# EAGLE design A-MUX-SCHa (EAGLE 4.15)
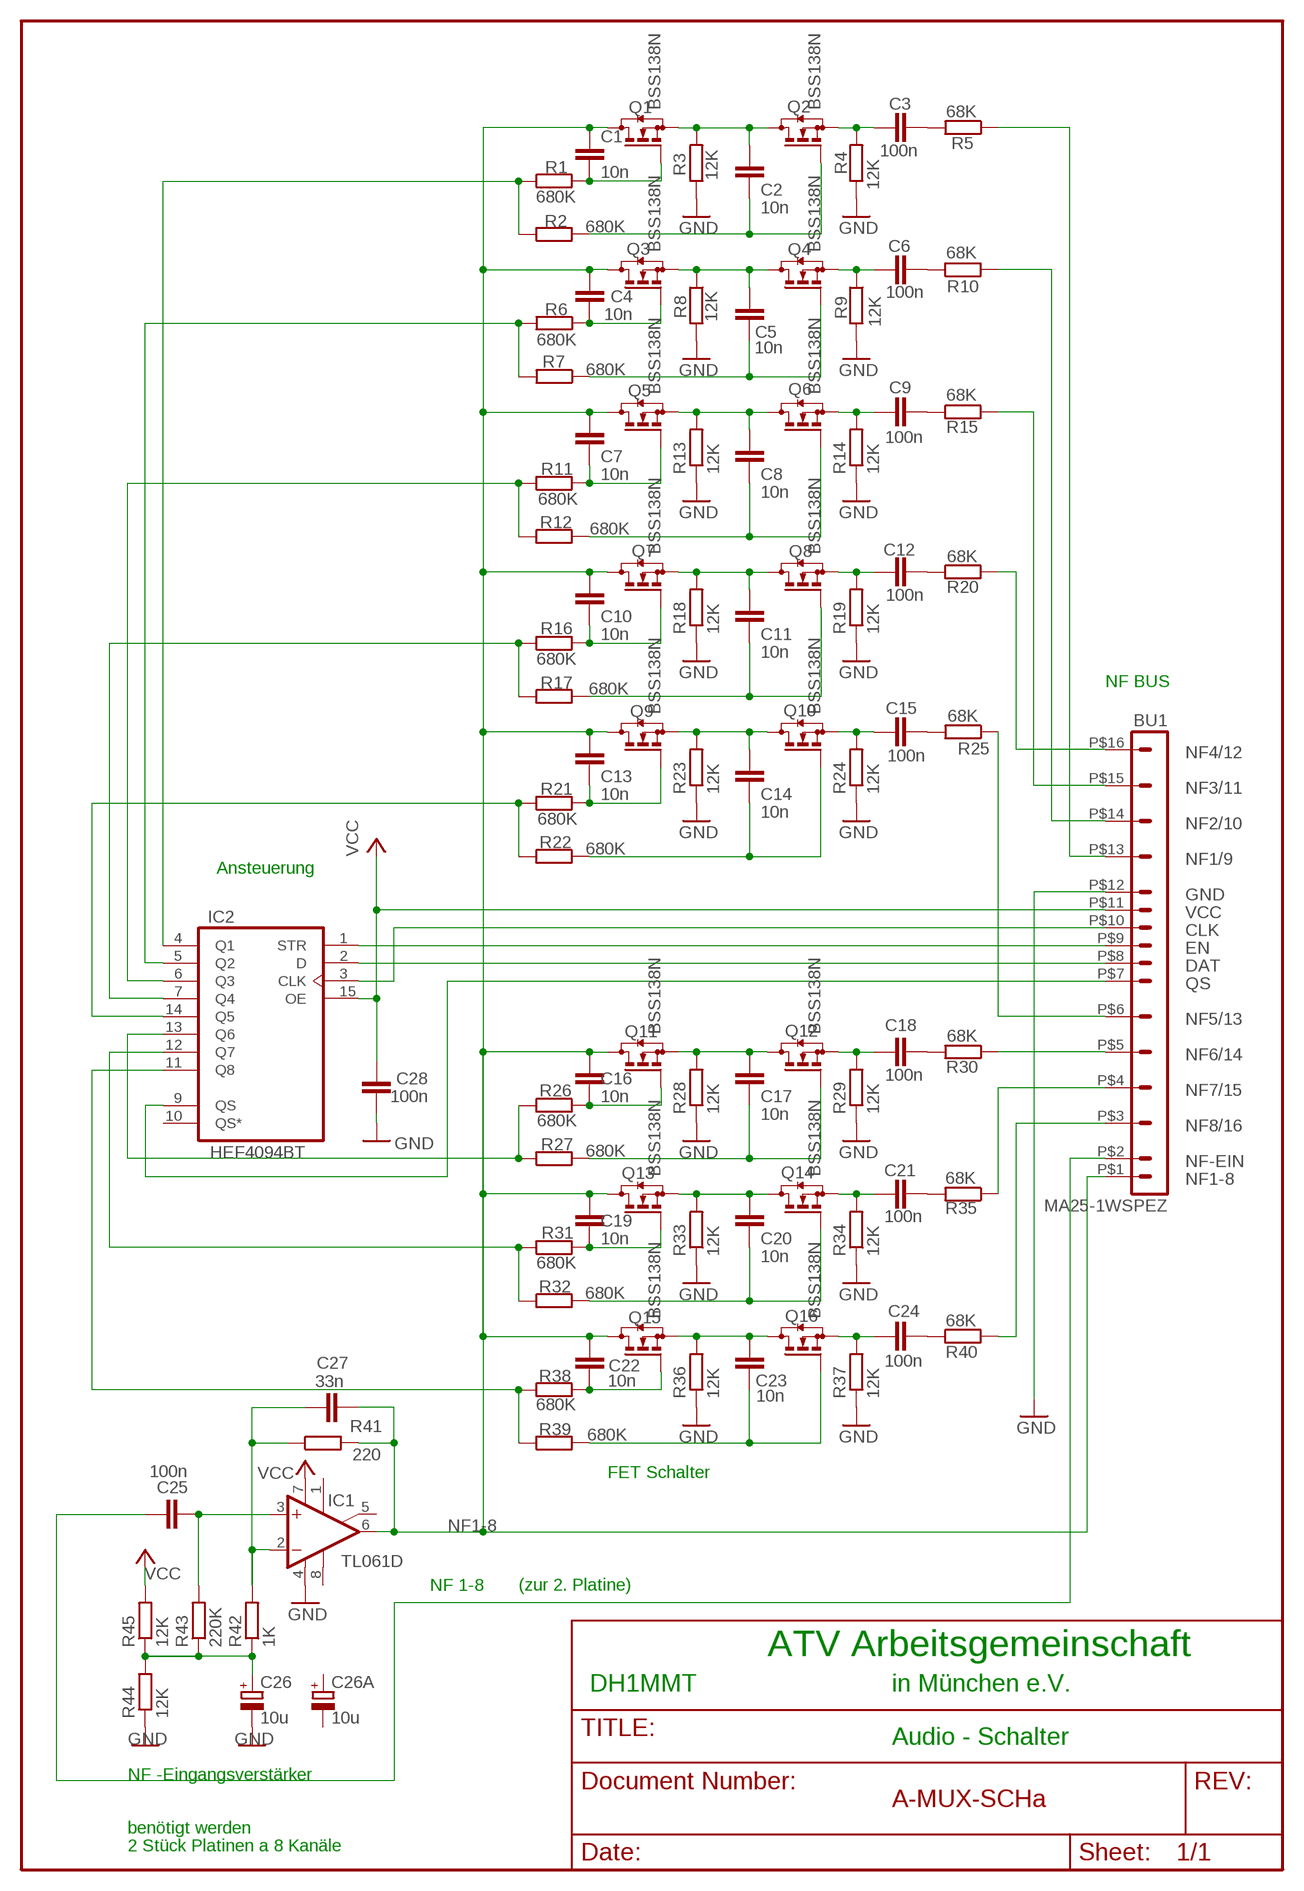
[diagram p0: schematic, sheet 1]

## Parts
BU1  MA25-1WSPEZ  [MA25-1WSPEZ]
C1  10n  C-EUC0603K  [C0603K]
C2  10n  C-EUC0603K  [C0603K]
C3  100n  C-EUC0603K  [C0603K]
C4  10n  C-EUC0603K  [C0603K]
C5  10n  C-EUC0603K  [C0603K]
C6  100n  C-EUC0603K  [C0603K]
C7  10n  C-EUC0603K  [C0603K]
C8  10n  C-EUC0603K  [C0603K]
C9  100n  C-EUC0603K  [C0603K]
C10  10n  C-EUC0603K  [C0603K]
C11  10n  C-EUC0603K  [C0603K]
C12  100n  C-EUC0603K  [C0603K]
C13  10n  C-EUC0603K  [C0603K]
C14  10n  C-EUC0603K  [C0603K]
C15  100n  C-EUC0603K  [C0603K]
C16  10n  C-EUC0603K  [C0603K]
C17  10n  C-EUC0603K  [C0603K]
C18  100n  C-EUC0603K  [C0603K]
C19  10n  C-EUC0603K  [C0603K]
C20  10n  C-EUC0603K  [C0603K]
C21  100n  C-EUC0603K  [C0603K]
C22  10n  C-EUC0603K  [C0603K]
C23  10n  C-EUC0603K  [C0603K]
C24  100n  C-EUC0603K  [C0603K]
C25  100n  C-EUC0603K  [C0603K]
C26  10u  CPOL-EUSMCB  [SMC_B]
C26A  10u  CPOL-EUE1.8-4  [E1,8-4]
C27  33n  C-EUC0603K  [C0603K]
C28  100n  C-EUC0603K  [C0603K]
IC1  TL061D  [SO08]
IC2  HEF4094BT  4094D  [SO16]
Q1  BSS138N  BSS123  [SOT23]
Q2  BSS138N  BSS123  [SOT23]
Q3  BSS138N  BSS123  [SOT23]
Q4  BSS138N  BSS123  [SOT23]
Q5  BSS138N  BSS123  [SOT23]
Q6  BSS138N  BSS123  [SOT23]
Q7  BSS138N  BSS123  [SOT23]
Q8  BSS138N  BSS123  [SOT23]
Q9  BSS138N  BSS123  [SOT23]
Q10  BSS138N  BSS123  [SOT23]
Q11  BSS138N  BSS123  [SOT23]
Q12  BSS138N  BSS123  [SOT23]
Q13  BSS138N  BSS123  [SOT23]
Q14  BSS138N  BSS123  [SOT23]
Q15  BSS138N  BSS123  [SOT23]
Q16  BSS138N  BSS123  [SOT23]
R1  680K  R-EU_MELF0204W  [MINI_MELF-0204W]
R2  680K  R-EU_MELF0204W  [MINI_MELF-0204W]
R3  12K  R-EU_MELF0204W  [MINI_MELF-0204W]
R4  12K  R-EU_MELF0204W  [MINI_MELF-0204W]
R5  68K  R-EU_MELF0204W  [MINI_MELF-0204W]
R6  680K  R-EU_MELF0204W  [MINI_MELF-0204W]
R7  680K  R-EU_MELF0204W  [MINI_MELF-0204W]
R8  12K  R-EU_MELF0204W  [MINI_MELF-0204W]
R9  12K  R-EU_MELF0204W  [MINI_MELF-0204W]
R10  68K  R-EU_MELF0204W  [MINI_MELF-0204W]
R11  680K  R-EU_MELF0204W  [MINI_MELF-0204W]
R12  680K  R-EU_MELF0204W  [MINI_MELF-0204W]
R13  12K  R-EU_MELF0204W  [MINI_MELF-0204W]
R14  12K  R-EU_MELF0204W  [MINI_MELF-0204W]
R15  68K  R-EU_MELF0204W  [MINI_MELF-0204W]
R16  680K  R-EU_MELF0204W  [MINI_MELF-0204W]
R17  680K  R-EU_MELF0204W  [MINI_MELF-0204W]
R18  12K  R-EU_MELF0204W  [MINI_MELF-0204W]
R19  12K  R-EU_MELF0204W  [MINI_MELF-0204W]
R20  68K  R-EU_MELF0204W  [MINI_MELF-0204W]
R21  680K  R-EU_MELF0204W  [MINI_MELF-0204W]
R22  680K  R-EU_MELF0204W  [MINI_MELF-0204W]
R23  12K  R-EU_MELF0204W  [MINI_MELF-0204W]
R24  12K  R-EU_MELF0204W  [MINI_MELF-0204W]
R25  68K  R-EU_MELF0204W  [MINI_MELF-0204W]
R26  680K  R-EU_MELF0204W  [MINI_MELF-0204W]
R27  680K  R-EU_MELF0204W  [MINI_MELF-0204W]
R28  12K  R-EU_MELF0204W  [MINI_MELF-0204W]
R29  12K  R-EU_MELF0204W  [MINI_MELF-0204W]
R30  68K  R-EU_MELF0204W  [MINI_MELF-0204W]
R31  680K  R-EU_MELF0204W  [MINI_MELF-0204W]
R32  680K  R-EU_MELF0204W  [MINI_MELF-0204W]
R33  12K  R-EU_MELF0204W  [MINI_MELF-0204W]
R34  12K  R-EU_MELF0204W  [MINI_MELF-0204W]
R35  68K  R-EU_MELF0204W  [MINI_MELF-0204W]
R36  12K  R-EU_MELF0204W  [MINI_MELF-0204W]
R37  12K  R-EU_MELF0204W  [MINI_MELF-0204W]
R38  680K  R-EU_MELF0204W  [MINI_MELF-0204W]
R39  680K  R-EU_MELF0204W  [MINI_MELF-0204W]
R40  68K  R-EU_MELF0204W  [MINI_MELF-0204W]
R41  220  R-EU_MELF0204W  [MINI_MELF-0204W]
R42  1K  R-EU_MELF0204W  [MINI_MELF-0204W]
R43  220K  R-EU_MELF0204W  [MINI_MELF-0204W]
R44  12K  R-EU_MELF0204W  [MINI_MELF-0204W]
R45  12K  R-EU_0207/10  [0207/10]

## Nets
CLK: BU1.P$10 IC2.3(CLK)
DAT: BU1.P$8 IC2.2(D)
EN: BU1.P$9 IC2.1(STR)
GND: BU1.P$12 C26.- C28.2 IC1.4(V-) R3.1 R4.1 R8.2 R9.2 R13.1 R14.1 R18.1 R19.1 R23.1 R24.1 R28.1 R29.1 R33.1 R34.1 R36.1 R37.1 R44.1
N$2: C1.2 Q1.1(G) R1.2
N$4: C2.1 Q1.2(S) Q2.3(D) R3.2
N$5: C2.2 Q2.1(G) R2.2
N$6: C3.1 Q2.2(S) R4.2
N$8: C3.2 R5.2
N$9: IC2.4(Q1) R1.1 R2.1
N$10: IC2.5(Q2) R6.2 R7.2
N$11: C4.1 Q3.1(G) R6.1
N$13: C5.2 Q3.2(S) Q4.3(D) R8.1
N$14: C5.1 Q4.1(G) R7.1
N$15: C6.1 R10.1
N$16: C6.2 Q4.2(S) R9.1
N$27: C9.1 R15.1
N$28: C12.1 R20.1
N$29: IC2.6(Q3) R11.1 R12.1
N$30: IC2.7(Q4) R16.1 R17.1
N$32: C11.1 Q7.2(S) Q8.3(D) R18.2
N$33: C12.2 Q8.2(S) R19.2
N$34: C11.2 Q8.1(G) R17.2
N$35: IC2.14(Q5) R21.1 R22.1
N$36: C10.2 Q7.1(G) R16.2
N$37: C7.2 Q5.1(G) R11.2
N$38: C8.2 Q6.1(G) R12.2
N$40: C8.1 Q5.2(S) Q6.3(D) R13.2
N$41: C9.2 Q6.2(S) R14.2
N$42: C13.2 Q9.1(G) R21.2
N$43: C14.2 Q10.1(G) R22.2
N$44: C15.2 Q10.2(S) R24.2
N$45: C14.1 Q9.2(S) Q10.3(D) R23.2
N$47: C15.1 R25.2
N$56: C18.1 R30.2
N$57: IC2.13(Q6) R26.1 R27.1
N$58: C17.2 Q12.1(G) R27.2
N$59: C18.2 Q12.2(S) R29.2
N$60: C17.1 Q11.2(S) Q12.3(D) R28.2
N$61: C16.2 Q11.1(G) R26.2
N$63: C21.1 R35.2
N$64: IC2.12(Q7) R31.1 R32.1
N$65: C20.2 Q14.1(G) R32.2
N$66: C19.2 Q13.1(G) R31.2
N$68: C20.1 Q13.2(S) Q14.3(D) R33.2
N$69: C21.2 Q14.2(S) R34.2
N$70: C24.1 R40.1
N$71: C23.1 Q15.2(S) Q16.3(D) R36.2
N$72: C22.2 Q15.1(G) R38.2
N$74: C23.2 Q16.1(G) R39.2
N$75: C24.2 Q16.2(S) R37.2
N$76: IC2.11(Q8) R38.1 R39.1
N$110: C25.2 IC1.3(+IN) R43.2
N$119: C27.1 IC1.2(-IN) R41.1 R42.2
N$152: C26.+ R42.1 R43.1 R44.2 R45.1
NF1-8: BU1.P$1 C1.1 C4.2 C7.1 C10.1 C13.1 C16.1 C19.1 C22.1 C27.2 IC1.6(OUT) Q1.3(D) Q3.3(D) Q5.3(D) Q7.3(D) Q9.3(D) Q11.3(D) Q13.3(D) Q15.3(D) R41.2
NF1/9: BU1.P$13 R5.1
NF2/10: BU1.P$14 R10.2
NF3/11: BU1.P$15 R15.2
NF4/12: BU1.P$16 R20.2
NF5/13: BU1.P$6 R25.1
NF6/14: BU1.P$5 R30.1
NF7/15: BU1.P$4 R35.1
NF8/16: BU1.P$3 R40.2
NF-EIN: BU1.P$2 C25.1
QS: BU1.P$7 IC2.9(QS)
VCC: BU1.P$11 C28.1 IC1.7(V+) IC2.15(OE) R45.2
Unconnected: C26A.+ C26A.- IC1.1(ON1) IC1.5(ON2) IC1.8(OPT) IC2.10(QS*)

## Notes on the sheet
- NF BUS
- Ansteuerung
- FET Schalter
- NF 1-8 | (zur 2. Platine)
- ATV Arbeitsgemeinschaft
- DH1MMT | in München e.V.
- Audio - Schalter
- NF -Eingangsverstärker
- benötigt werden
- 2 Stück Platinen a 8 Kanäle

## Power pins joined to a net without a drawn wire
VDD: IC2.16(VDD)
VSS: IC2.8(VSS)

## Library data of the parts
BU1 = con-lstb:MA25-1WSPEZ
C1-C25 C27 C28 = rcl:C-EU: CAPACITOR, European symbol
C26 C26A = rcl:CPOL-EU: POLARIZED CAPACITOR, European symbol
IC1 = linear:TL061: OP AMP
IC2 = 40xx:4094: 8-stage SHIFT/STORE REGISTER, tri-state
Q1-Q16 = transistor-small-signal:BSS123: N-CHANNEL MOS FET
R1-R45 = rcl:R-EU_: RESISTOR, European symbol

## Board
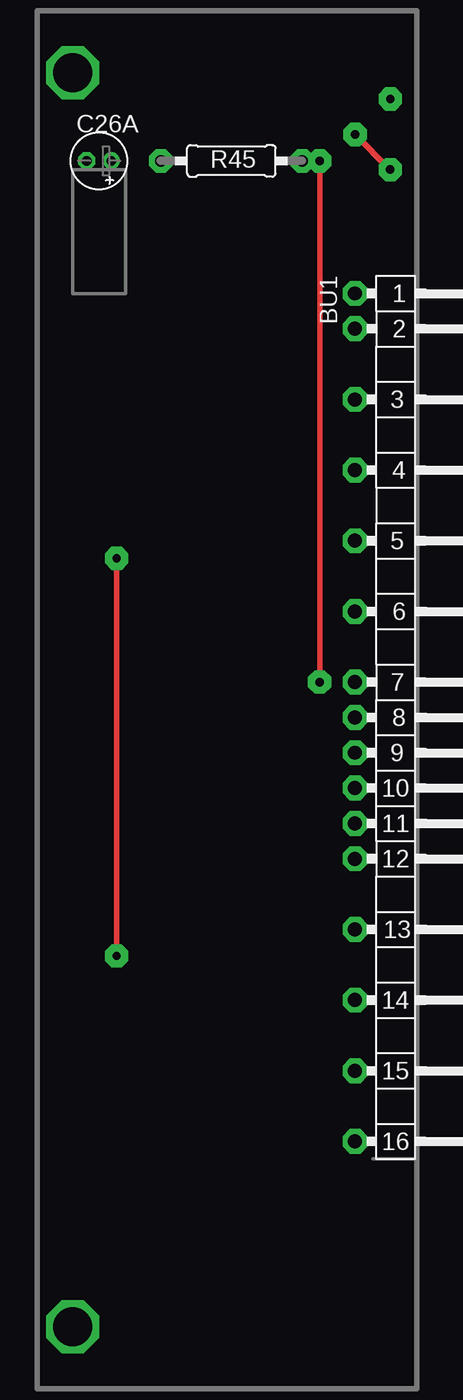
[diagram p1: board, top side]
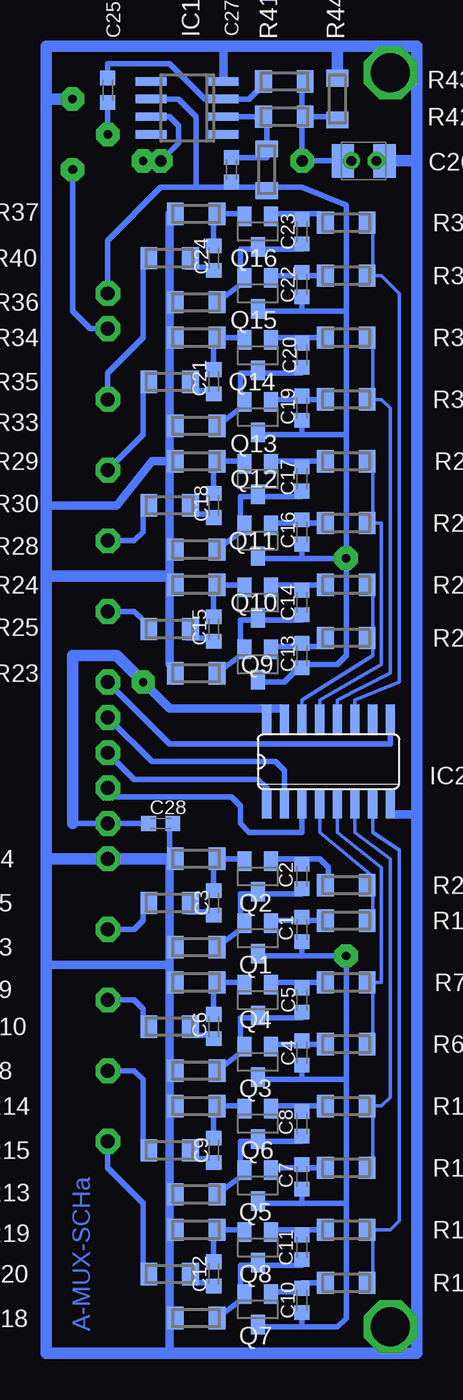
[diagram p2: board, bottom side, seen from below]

No outline drawn. Coordinates in mm, seen from the top.
Copper layers (1*16): Top 0.035mm / dielectric 1.5mm / Bottom 0.035mm
Design rules "default": minimum track width 10mil, minimum drill 24mil, track to track 8mil, track to pad 8mil, pad to pad 8mil, via to via 8mil, smd to smd 8mil, copper to edge 40mil, drill to drill 8mil, minimum pad ring 10mil, minimum via ring 8mil, stop-mask expansion 4mil, vias tented up to drill 0mil, thermal gap 10mil

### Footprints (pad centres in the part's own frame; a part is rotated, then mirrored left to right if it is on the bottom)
MA25-1WSPEZ = drill 1 pad 1.778 octagon: P$1 2.54,30.48; P$2 2.54,27.94; P$3 2.54,22.86; P$4 2.54,17.78; P$5 2.54,12.7; P$6 2.54,7.62; P$7 2.54,2.54; P$8 2.54,0; P$9 2.54,-2.54; P$10 2.54,-5.08; P$11 2.54,-7.62; P$12 2.54,-10.16; P$13 2.54,-15.24; P$14 2.54,-20.32; P$15 2.54,-25.4; P$16 2.54,-30.48
C0603K = smd 1.05 x 1.08: 1 -0.875,0; 2 0.875,0
SMC_B = smd 1.6 x 2.4: + -1.5,0; - 1.5,0
E1,8-4 = drill 0.711 pad 1.168 round: + -0.889,0 | drill 0.711 pad 1.168 octagon: - 0.889,0
SO08 = smd 0.6 x 2.2: 1 -1.905,-2.6; 2 -0.635,-2.6; 3 0.635,-2.6; 4 1.905,-2.6; 5 1.905,2.6; 6 0.635,2.6; 7 -0.635,2.6; 8 -1.905,2.6
SO16 = smd 0.66 x 2.032: 1 -4.445,-3.073; 2 -3.175,-3.073; 3 -1.905,-3.073; 4 -0.635,-3.073; 5 0.635,-3.073; 6 1.905,-3.073; 7 3.175,-3.073; 8 4.445,-3.073; 9 4.445,3.073; 10 3.175,3.073; 11 1.905,3.073; 12 0.635,3.073; 13 -0.635,3.073; 14 -1.905,3.073; 15 -3.175,3.073; 16 -4.445,3.073
SOT23 = smd 1 x 1.4: 1 -0.95,-1.1; 2 0.95,-1.1; 3 0,1.1
MINI_MELF-0204W = smd 1.2 x 1.6: 1 -1.5,0; 2 1.5,0
0207/10 = drill 0.813 octagon: 1 -5.08,0; 2 5.08,0

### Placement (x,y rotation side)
BU1  126.36,93.34 0 top
C1  114.94,78.11 90 bottom
C2  114.94,81.92 90 bottom
C3  121.28,80.01 270 bottom
C4  114.94,69.22 270 bottom
C5  114.94,73.03 270 bottom
C6  121.28,71.12 90 bottom
C7  114.94,60.33 90 bottom
C8  114.94,64.14 90 bottom
C9  121.28,62.23 90 bottom
C10  114.94,51.44 90 bottom
C11  114.94,55.24 90 bottom
C12  121.28,53.34 90 bottom
C13  114.94,97.79 90 bottom
C14  114.94,101.6 90 bottom
C15  121.28,99.69 90 bottom
C16  114.94,106.68 90 bottom
C17  114.94,110.49 90 bottom
C18  121.28,108.58 90 bottom
C19  114.94,115.57 90 bottom
C20  114.94,119.38 90 bottom
C21  121.28,117.47 90 bottom
C22  114.94,124.46 90 bottom
C23  114.94,128.27 90 bottom
C24  121.28,126.36 90 bottom
C25  128.91,138.43 90 bottom
C26  110.49,133.35 0 bottom
C26A  110.49,133.35 180 top
C27  120.02,132.72 270 bottom
C28  125.09,85.72 0 bottom
IC1  123.19,137.16 90 bottom
IC2  113.03,90.17 0 bottom
Q1  118.11,77.47 180 bottom
Q2  118.11,81.92 180 bottom
Q3  118.11,68.58 180 bottom
Q4  118.11,73.03 180 bottom
Q5  118.11,59.69 180 bottom
Q6  118.11,64.14 180 bottom
Q7  118.11,50.8 180 bottom
Q8  118.11,55.24 180 bottom
Q9  118.11,97.16 180 bottom
Q10  118.11,101.6 180 bottom
Q11  118.11,106.05 180 bottom
Q12  118.11,110.49 180 bottom
Q13  118.11,114.94 180 bottom
Q14  118.11,119.38 180 bottom
Q15  118.11,123.83 180 bottom
Q16  118.11,128.27 180 bottom
R1  111.76,78.74 180 bottom
R2  111.76,81.28 180 bottom
R3  122.56,76.83 0 bottom
R4  122.56,83.19 0 bottom
R5  124.46,80.01 0 bottom
R6  111.76,69.85 0 bottom
R7  111.76,74.3 0 bottom
R8  122.56,67.94 180 bottom
R9  122.56,74.3 180 bottom
R10  124.46,71.12 180 bottom
R11  111.76,60.96 180 bottom
R12  111.76,65.41 180 bottom
R13  122.56,59.05 0 bottom
R14  122.56,65.41 0 bottom
R15  124.46,62.23 180 bottom
R16  111.76,52.7 180 bottom
R17  111.76,56.52 180 bottom
R18  122.56,50.16 0 bottom
R19  122.56,56.52 0 bottom
R20  124.46,53.34 180 bottom
R21  111.76,99.06 180 bottom
R22  111.76,102.87 180 bottom
R23  122.56,96.52 0 bottom
R24  122.56,102.87 0 bottom
R25  124.46,99.69 0 bottom
R26  111.76,107.31 180 bottom
R27  111.76,111.76 180 bottom
R28  122.56,105.41 0 bottom
R29  122.56,111.76 0 bottom
R30  124.46,108.58 0 bottom
R31  111.76,116.2 180 bottom
R32  111.76,120.65 180 bottom
R33  122.56,114.3 0 bottom
R34  122.56,120.65 0 bottom
R35  124.46,117.47 0 bottom
R36  122.56,123.19 0 bottom
R37  122.56,129.54 0 bottom
R38  111.76,125.09 180 bottom
R39  111.76,128.91 180 bottom
R40  124.46,126.36 180 bottom
R41  117.47,132.72 270 bottom
R42  116.2,136.53 180 bottom
R43  116.2,139.06 180 bottom
R44  112.39,137.79 270 bottom
R45  120.02,133.35 0 top
U$2  [DINA4_L]  -0.64,-0.64 0 top

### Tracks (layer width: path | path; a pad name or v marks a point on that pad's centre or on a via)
CLK
  Bottom 0.406: IC2.3 114.94,85.09 118.75,85.09 119.38,85.72 119.38,87 120.02,87.63 128.27,87.63 BU1.P$10
DAT
  Bottom 0.406: 116.2,87 116.2,86.36 | 116.2,87 IC2.2 | 116.2,87 116.2,89.53 116.84,90.17 125.73,90.17 BU1.P$8
EN
  Bottom 0.406: 117.47,87 IC2.1 117.47,88.27 118.11,88.9 127,88.9 BU1.P$9
GND  (via drill 0.6 pad 1.68)
  Bottom 0.406: 119.38,141.6 120.59,141.54 | 124.46,129.54 R37.1 | 124.46,123.19 R36.1 | 124.46,120.65 R34.1 | 124.46,114.3 R33.1 | 124.46,111.76 R29.1 | 124.46,106.05 R28.1 | 124.46,103.5 R24.1 | 124.46,97.16 R23.1 | 124.46,76.83 R3.1 | 124.46,74.3 R9.2 | 124.46,67.94 R8.2 | 124.46,65.41 R14.1 | 124.46,59.05 R13.1 | 124.46,56.52 R19.1 | 124.46,50.16 R18.1 | 130.81,141.6 131.43,141.59 | C28.2 124.46,85.72 124.46,83.19 R4.1
  Bottom 0.61: 106.68,86.36 108.58,86.36 | 120.59,141.54 IC1.4 | 124.46,129.54 124.46,123.19 124.46,120.65 124.46,114.3 124.46,111.76 | 124.46,111.76 124.46,106.05 124.46,103.5 124.46,97.16 | 124.46,83.19 124.46,76.83 124.46,75.56 | 124.46,75.56 124.46,74.3 124.46,67.94 124.46,65.41 124.46,59.05 124.46,56.52 124.46,50.16 124.46,47.62 | 133.35,108.58 128.27,108.58 125.73,111.76 124.46,111.76 | 133.35,75.56 124.46,75.56
  Bottom 0.813: 106.68,133.35 106.68,141.6 112.39,141.6 | 106.68,133.35 106.68,86.36 106.68,47.62 124.46,47.62 133.35,47.62 133.35,75.56 133.35,83.19 | 112.39,141.6 119.38,141.6 130.81,141.6 133.35,141.6 133.35,137.79 | 133.35,137.79 133.35,108.58 133.35,103.5 | 133.35,103.5 133.35,83.19 | 133.35,103.5 124.46,103.5 | 106.68,133.35 C26.- | 133.35,137.79 v131.44,137.79 | 112.39,141.6 R44.1 | 133.35,83.19 BU1.P$12 124.46,83.19
N$2
  Bottom 0.406: Q1.1 117.31,78.57 117.47,78.74 114.94,78.74 | R1.2 113.26,78.33 113.67,78.74 114.94,78.74 | 114.94,78.74 C1.2
N$4
  Bottom 0.406: C2.1 114.94,80.64 118.11,80.64 | 118.11,80.64 Q2.3 | 118.11,80.64 119.38,80.64 119.38,78.11 | 119.38,78.11 119.21,78.57 Q1.2 118.75,78.57 119.38,78.11 | 119.38,78.11 R3.2
N$5
  Bottom 0.406: Q2.1 117.01,83.02 116.84,83.19 114.94,83.19 | 114.94,83.19 C2.2 | 114.94,83.19 113.67,83.19 113.03,82.55 113.03,81.28 R2.2
N$6
  Bottom 0.406: 121.28,83.19 C3.1 | R4.2 121.28,83.19 | Q2.2 119.38,83.02 119.38,83.19 121.28,83.19
N$8
  Bottom 0.406: C3.2 121.28,79.38 123.19,79.38 122.96,79.61 R5.2 122.56,80.01
N$9
  Bottom 0.254: IC2.4 113.67,85.09 109.86,81.92 | R1.1 109.86,78.11 109.86,81.92 | R2.1 110.26,81.69 109.86,81.92
N$10
  Bottom 0.254: IC2.5 112.39,85.09 109.22,82.55 109.22,74.3 109.86,74.3 | 109.86,74.3 R7.2 | R6.2 109.86,69.85 109.86,74.3
N$11
  Bottom 0.406: Q3.1 117.01,69.68 116.84,69.85 114.94,69.85 | 114.94,69.85 C4.1 | 113.03,69.85 R6.1 114.94,69.85
N$13
  Bottom 0.406: 119.38,69.22 119.21,69.68 Q3.2 118.92,69.68 118.75,69.22 119.38,69.22 | 119.38,69.22 R8.1 | 119.38,69.22 119.38,71.75 118.11,71.75 | 118.11,71.75 Q4.3 | C5.2 114.94,71.75 118.11,71.75
N$14
  Bottom 0.406: Q4.1 117.01,74.12 116.84,74.3 114.94,74.3 | 114.94,74.3 C5.1 | 113.03,74.3 R7.1 114.94,74.3
N$15
  Bottom 0.406: C6.1 121.28,70.48 123.19,70.48 122.96,70.72 R10.1
N$16
  Bottom 0.406: 121.28,71.75 C6.2 121.28,74.3 | R9.1 121.28,74.3 | Q4.2 119.38,74.12 119.38,74.3 121.28,74.3
N$17  (via drill 0.9 pad 1.78)
  other vias: 128.91,90.81
N$18  (via drill 0.9 pad 1.78)
  other vias: 128.91,88.27
N$21  (via drill 0.9 pad 1.78)
  other vias: 128.91,100.97
N$24  (via drill 0.9 pad 1.78)
  other vias: 128.91,106.05
N$25  (via drill 0.9 pad 1.78)
  other vias: 128.91,111.12
N$26  (via drill 0.9 pad 1.78)
  other vias: 128.91,116.2
N$27
  Bottom 0.406: C9.1 121.28,61.59 123.19,61.59 123.19,62.23 R15.1
N$28
  Bottom 0.406: C12.1 121.28,52.7 123.19,52.7 122.96,52.94 R20.1
N$29
  Bottom 0.254: IC2.6 111.12,85.09 108.58,83.19 108.58,66.04 109.22,65.41 109.86,65.41 | 109.86,65.41 R12.1 | R11.1 109.86,60.96 109.86,65.41
N$30
  Bottom 0.254: IC2.7 109.86,85.09 107.95,83.82 107.95,57.15 108.58,56.52 109.86,56.52 | 109.86,56.52 R17.1 | R16.1 109.86,52.07 109.86,56.52
N$31  (via drill 0.9 pad 1.78)
  other vias: 128.91,78.11
N$32
  Bottom 0.406: C11.1 114.94,53.98 118.11,53.98 | 118.11,53.98 Q8.3 | 118.11,53.98 119.38,53.98 119.38,51.9 | 119.38,51.9 Q7.2 | 119.38,51.9 119.38,51.44 R18.2
N$33
  Bottom 0.406: Q8.2 118.75,56.34 119.38,56.52 R19.2 121.28,56.52 C12.2
N$34
  Bottom 0.406: 117.31,56.34 Q8.1 117.16,56.2 | 114.94,56.52 116.84,56.52 117.16,56.2 | 114.94,56.52 C11.2 | 113.03,56.52 R17.2 114.94,56.52 | 117.16,56.2 117.47,55.88
N$35
  Bottom 0.254: IC2.14 114.94,94.61 109.86,97.79 109.86,99.06 | 109.86,99.06 R21.1 | R22.1 109.86,102.87 109.86,99.06
N$36
  Bottom 0.406: Q7.1 117.01,51.9 116.84,52.07 114.94,52.07 114.94,52.7 | 114.94,52.7 C10.2 | 113.03,52.7 R16.2 114.94,52.7
N$37
  Bottom 0.406: Q5.1 117.01,60.79 116.84,60.96 114.94,60.96 | 114.94,60.96 C7.2 | 113.03,60.96 R11.2 114.94,60.96
N$38
  Bottom 0.406: Q6.1 117.01,65.23 116.84,65.41 114.94,65.41 | 114.94,65.41 C8.2 | 113.03,65.41 R12.2 114.94,65.41
N$39  (via drill 0.9 pad 1.78)
  other vias: 128.91,73.03
N$40
  Bottom 0.406: C8.1 114.94,62.87 118.11,62.87 | 118.11,62.87 Q6.3 | 118.11,62.87 119.38,62.87 119.38,60.79 | 119.38,60.79 Q5.2 | 119.38,60.79 119.38,60.33 R13.2
N$41
  Bottom 0.406: 121.28,62.87 C9.2 121.28,65.41 | R14.2 121.28,65.41 | Q6.2 119.38,65.23 119.38,65.41 121.28,65.41
N$42
  Bottom 0.406: Q9.1 117.01,98.25 116.84,98.42 114.94,98.42 | 114.94,98.42 C13.2 | 114.94,98.42 113.03,98.42 113.03,99.06 R21.2
N$43
  Bottom 0.406: 113.03,102.87 R22.2 113.26,102.64 113.03,102.87 | Q10.1 117.01,102.7 116.84,102.87 114.94,102.87 | 114.94,102.87 C14.2 | 114.94,102.87 113.03,102.87
N$44
  Bottom 0.406: C15.2 121.28,102.87 R24.2 119.38,102.87 119.38,102.7 Q10.2
N$45
  Bottom 0.406: C14.1 114.94,100.33 118.11,100.33 | 118.11,100.33 Q10.3 | 118.11,100.33 119.38,100.33 119.38,97.79 | 119.38,97.79 R23.2 | Q9.2 119.06,98.11 119.38,97.79
N$47
  Bottom 0.406: C15.1 121.28,99.06 123.19,99.06 122.96,99.29 R25.2
N$50  (via drill 0.9 pad 1.78)
  other vias: 128.91,85.72
N$51  (via drill 2.8 pad 2.54)
  other vias: 108.58,139.7
N$53  (via drill 0.9 pad 1.78)
  other vias: 128.91,95.89
N$54  (via drill 2.8 pad 2.54)
  other vias: 108.58,49.53
N$55  (via drill 0.9 pad 1.78)
  other vias: 128.91,93.34
N$56
  Bottom 0.406: C18.1 121.28,107.95 123.19,107.95 123.19,108.58 R30.2
N$57
  Bottom 0.254: IC2.13 113.67,94.61 109.22,97.16 109.22,107.31 109.86,107.31 | 109.86,107.31 R26.1 | R27.1 109.86,111.76 109.86,107.31
N$58
  Bottom 0.406: Q12.1 117.01,111.59 116.84,111.76 114.94,111.76 | 114.94,111.76 C17.2 | 114.94,111.76 113.67,111.76 | 113.67,111.76 113.03,111.76 | 113.67,111.76 R27.2
N$59
  Bottom 0.406: C18.2 121.28,111.76 R29.2 118.75,111.76 118.75,111.59 Q12.2
N$60
  Bottom 0.406: 118.11,109.22 Q12.3 | C17.1 114.94,109.22 118.11,109.22 | 118.11,109.22 119.38,109.22 119.38,106.68 | Q11.2 118.75,107.14 119.38,106.68 | 119.38,106.68 R28.2
N$61
  Bottom 0.406: Q11.1 116.84,107.14 116.84,107.31 114.94,107.31 | 114.94,107.31 C16.2 | 113.03,107.31 R26.2 arc90 113.03,107.72 113.03,107.31 | 114.94,107.31 113.03,107.31
N$63
  Bottom 0.406: C21.1 121.28,116.84 123.19,116.84 123.19,117.47 R35.2
N$64
  Bottom 0.254: IC2.12 112.39,94.61 108.58,96.52 108.58,115.57 109.22,116.2 109.86,116.2 | 109.86,116.2 R31.1 | R32.1 109.86,120.65 109.86,116.2
N$65
  Bottom 0.406: 114.94,120.65 C20.2 | Q14.1 116.84,120.48 116.84,120.65 114.94,120.65 | 114.94,120.65 R32.2 113.03,120.65
N$66
  Bottom 0.406: 114.94,116.2 R31.2 113.03,116.2 | 114.94,116.2 C19.2 | Q13.1 116.84,116.03 116.84,116.2 114.94,116.2
N$68
  Bottom 0.406: C20.1 114.94,118.11 118.11,118.11 | 118.11,118.11 Q14.3 | 118.11,118.11 119.38,118.11 119.38,115.57 | Q13.2 118.75,116.03 119.38,115.57 | 119.38,115.57 R33.2
N$69
  Bottom 0.406: 121.28,118.11 C21.2 121.28,120.65 | R34.2 121.28,120.65 | Q14.2 119.38,120.48 119.38,120.65 121.28,120.65
N$70
  Bottom 0.406: C24.1 121.28,125.73 123.19,125.73 123.19,126.36 R40.1
N$71
  Bottom 0.406: C23.1 114.94,127 118.11,127 | 118.11,127 Q16.3 | 118.11,127 119.38,127 119.38,124.46 | 119.38,124.46 118.75,124.92 Q15.2 | 119.38,124.46 R36.2
N$72
  Bottom 0.406: 114.94,125.09 113.03,125.09 113.03,125.5 arc-90 R38.2 | 114.94,125.09 C22.2 | Q15.1 116.84,124.92 116.84,125.09 114.94,125.09
N$74
  Bottom 0.406: 114.94,129.54 C23.2 | Q16.1 116.84,129.37 116.84,129.54 114.94,129.54 | 114.94,129.54 113.67,129.54 113.03,128.91 R39.2
N$75
  Bottom 0.406: 121.28,129.54 C24.2 | R37.2 121.28,129.54 | Q16.2 119.38,129.37 119.38,129.54 121.28,129.54
N$76
  Bottom 0.254: IC2.11 111.12,94.61 107.95,95.89 107.95,123.83 109.22,125.09 109.86,125.09 | 109.86,125.09 R38.1 | R39.1 109.86,128.91 109.86,125.09
N$85  (via drill 0.6 pad 1.68)
  other vias: 131.44,132.72
N$86  (via drill 0.6 pad 1.68)
  other vias: 128.91,135.25
N$87  (via drill 0.6 pad 1.68)
  other vias: 125.09,133.35
N$88  (via drill 0.6 pad 1.68)
  other vias: 114.94,133.35
N$110
  Bottom 0.406: R43.2 117.47,139.06 118.75,137.79 IC1.3 121.92,137.79 124.46,140.34 128.91,140.34 C25.2 128.91,139.06
N$119
  Bottom 0.406: IC1.2 R42.2 117.47,136.53 117.47,133.58 | C27.1 120.02,133.35 119.78,133.58 117.47,133.58 | 117.47,133.58 R41.1
N$152  (via drill 0.6 pad 1.42)
  Top 0.406: R45.1 114.3,133.35
  Bottom 0.406: R43.1 114.94,139.06 114.94,136.53 | 114.94,136.53 R42.1 112.39,136.53 R44.2 | 114.94,136.53 R45.1 C26.+
  other vias: 114.94,133.35
NF1-8  (via drill 0.6 pad 1.68)
  Top 0.406: v111.76,104.78 v111.76,76.2
  Bottom 0.406: Q1.3 118.11,76.2 114.94,76.2 | C10.1 114.94,49.53 118.11,49.53 | 118.11,49.53 Q7.3 | 118.11,49.53 112.39,49.53 111.76,50.16 111.76,58.42 | Q5.3 118.11,58.42 114.94,58.42 | 114.94,58.42 C7.1 | Q3.3 118.11,67.31 114.94,67.31 | 114.94,67.31 C4.2 | C22.1 114.94,122.56 116.2,122.56 | Q15.3 118.11,122.56 116.2,122.56 | Q13.3 118.11,113.67 116.2,113.67 | C19.1 114.94,113.67 116.2,113.67 | Q11.3 118.11,104.78 114.94,104.78 | 114.94,104.78 C16.1 | Q9.3 118.11,95.89 116.2,95.89 114.94,97.16 | 122.56,131.44 122.56,136.53 123.83,137.79 IC1.6 | 111.76,113.67 v111.76,104.78 | 111.76,113.67 116.2,113.67 | 111.76,122.56 116.2,122.56 | 111.76,122.56 111.76,113.67 | v111.76,104.78 114.94,104.78 | 111.76,122.56 111.76,130.18 114.94,131.44 116.84,131.44 | 114.94,76.2 C1.1 | 114.94,76.2 v111.76,76.2 111.76,67.31 | 111.76,67.31 114.94,67.31 | 111.76,67.31 111.76,58.42 | 111.76,58.42 114.94,58.42 | v111.76,104.78 111.76,97.79 112.39,97.16 114.94,97.16 | 114.94,97.16 C13.1 | 120.02,131.44 116.84,131.44 | 120.02,132.08 C27.2 120.02,131.44 | 122.56,131.44 120.02,131.44 | R41.2 117.07,131.22 116.84,131.44 | 122.56,131.44 125.09,131.44 128.91,127.64 BU1.P$1
NF1/9
  Bottom 0.406: R5.1 126.36,80.01 126.36,78.74 127,78.11 BU1.P$13
NF2/10
  Bottom 0.406: R10.2 126.36,71.12 126.36,72.39 127,73.03 BU1.P$14
NF3/11
  Bottom 0.406: R15.2 126.36,62.23 126.36,67.31 127,67.94 BU1.P$15
NF4/12
  Bottom 0.406: R20.2 126.36,53.34 126.36,58.42 128.91,60.96 BU1.P$16
NF5/13
  Bottom 0.406: R25.1 126.36,99.69 126.36,100.33 127,100.97 BU1.P$6
NF6/14
  Bottom 0.406: R30.1 126.36,108.58 126.36,106.68 127,106.05 BU1.P$5
NF7/15
  Bottom 0.406: R35.1 126.36,117.47 126.36,113.67 BU1.P$4
NF8/16
  Bottom 0.406: R40.2 126.36,126.36 126.36,120.65 128.91,118.11 BU1.P$3
NF-EIN  (via drill 0.6)
  Top 0.406: v131.43,132.74 v128.91,135.25
  Bottom 0.406: v131.43,132.74 131.44,132.72 131.44,122.56 130.18,121.28 BU1.P$2 | v128.91,135.25 C25.1
QS
  Bottom 0.406: IC2.9 108.58,91.44 124.46,91.44 BU1.P$7
VCC  (via drill 0.6 pad 1.42, 0.6 pad 1.68)
  Top 0.406: v126.36,133.35 v126.36,95.89
  Bottom 0.406: IC1.7 124.46,136.53 123.83,135.89 123.83,134.62 R45.2 v126.36,133.35 | 116.2,93.98 IC2.15 | 125.73,85.72 C28.1 BU1.P$11 131.44,85.72
  Bottom 0.61: v126.36,95.89 124.46,93.98 116.2,93.98
  Bottom 0.813: 131.44,85.72 131.44,97.79 128.27,97.79 v126.36,95.89
  other vias: 125.09,133.35

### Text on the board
Bottom: A-MUX-SCHa
tDocu: NF 1-8 | NF Ein | NF BUS 8 | /16 | NF BUS 7 | /15 | NF BUS 6 | /14 | NF BUS 5 | /13 | QS | DAT | EN | CLK | VCC | GND | NF BUS 1 | /9 | NF BUS 2 | /10 | NF BUS 3 | /11 | NF BUS 4 | /12 | Audio - Schalter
